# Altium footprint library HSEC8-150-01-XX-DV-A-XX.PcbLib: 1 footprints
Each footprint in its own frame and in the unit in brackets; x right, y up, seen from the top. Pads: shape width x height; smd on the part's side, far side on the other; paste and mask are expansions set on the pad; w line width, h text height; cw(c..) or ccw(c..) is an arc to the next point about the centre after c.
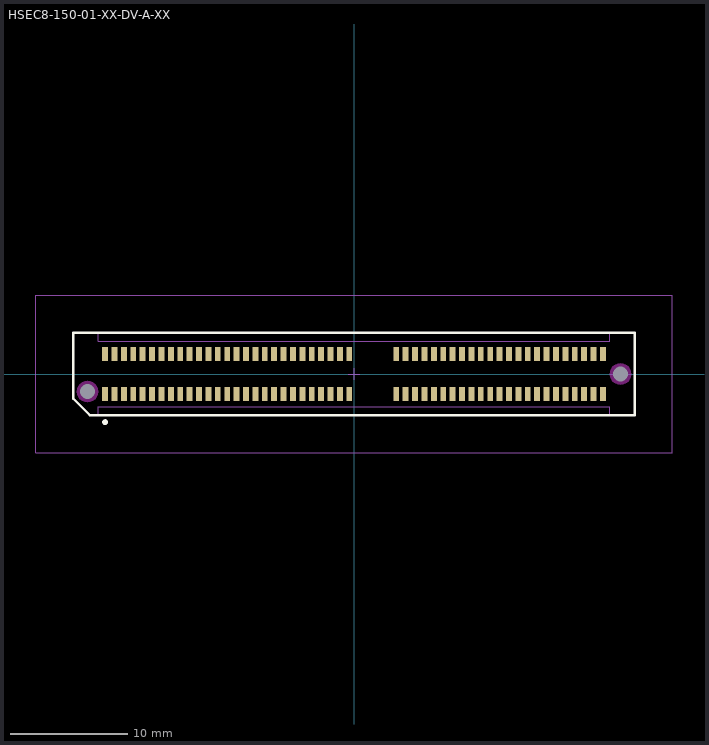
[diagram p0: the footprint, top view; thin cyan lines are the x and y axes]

## HSEC8-150-01-XX-DV-A-XX [mm] "0.80mm pitch, high-speed connector; socket (female), w/alignment pins, SMT"
height 7.98
pads (102):
  rect 0.5x1.2 smd mask+0: 1(-21.2,-1.7) 2(-21.2,1.7) 3(-20.4,-1.7) 4(-20.4,1.7) 5(-19.6,-1.7) 6(-19.6,1.7) 7(-18.8,-1.7) 8(-18.8,1.7) 9(-18,-1.7) 10(-18,1.7) 11(-17.2,-1.7) 12(-17.2,1.7) 13(-16.4,-1.7) 14(-16.4,1.7) 15(-15.6,-1.7) 16(-15.6,1.7) 17(-14.8,-1.7) 18(-14.8,1.7) 19(-14,-1.7) 20(-14,1.7) 21(-13.2,-1.7) 22(-13.2,1.7) 23(-12.4,-1.7) 24(-12.4,1.7) 25(-11.6,-1.7) 26(-11.6,1.7) 27(-10.8,-1.7) 28(-10.8,1.7) 29(-10,-1.7) 30(-10,1.7) 31(-9.2,-1.7) 32(-9.2,1.7) 33(-8.4,-1.7) 34(-8.4,1.7) 35(-7.6,-1.7) 36(-7.6,1.7) 37(-6.8,-1.7) 38(-6.8,1.7) 39(-6,-1.7) 40(-6,1.7) 41(-5.2,-1.7) 42(-5.2,1.7) 43(-4.4,-1.7) 44(-4.4,1.7) 45(-3.6,-1.7) 46(-3.6,1.7) 47(-2.8,-1.7) 48(-2.8,1.7) 49(-2,-1.7) 50(-2,1.7) 51(-1.2,-1.7) 52(-1.2,1.7) 53(-0.4,-1.7) 54(-0.4,1.7) 55(3.6,-1.7) 56(3.6,1.7) 57(4.4,-1.7) 58(4.4,1.7) 59(5.2,-1.7) 60(5.2,1.7) 61(6,-1.7) 62(6,1.7) 63(6.8,-1.7) 64(6.8,1.7) 65(7.6,-1.7) 66(7.6,1.7) 67(8.4,-1.7) 68(8.4,1.7) 69(9.2,-1.7) 70(9.2,1.7) 71(10,-1.7) 72(10,1.7) 73(10.8,-1.7) 74(10.8,1.7) 75(11.6,-1.7) 76(11.6,1.7) 77(12.4,-1.7) 78(12.4,1.7) 79(13.2,-1.7) 80(13.2,1.7) 81(14,-1.7) 82(14,1.7) 83(14.8,-1.7) 84(14.8,1.7) 85(15.6,-1.7) 86(15.6,1.7) 87(16.4,-1.7) 88(16.4,1.7) 89(17.2,-1.7) 90(17.2,1.7) 91(18,-1.7) 92(18,1.7) 93(18.8,-1.7) 94(18.8,1.7) 95(19.6,-1.7) 96(19.6,1.7) 97(20.4,-1.7) 98(20.4,1.7) 99(21.2,-1.7) 100(21.2,1.7)
  round 1 hole 1.3 unplated mask+0: 101(-22.7,-1.5) 102(22.7,0)
Top Overlay:
  circle w0.25: c-21.2,-4.1 r0.125
  lines w0.2: -23.9,-2.1 -23.9,3.5 23.9,3.5 23.9,-3.5 -22.5,-3.5 -23.9,-2.1
Keep-Out Layer:
  pour cut-out: 23.608,0 23.577,0.235 23.486,0.454 23.342,0.642 23.154,0.786 22.935,0.877 22.7,0.908 22.465,0.877 22.246,0.786 22.058,0.642 21.914,0.454 21.823,0.235 21.792,0 21.823,-0.235 21.914,-0.454 22.058,-0.642 22.246,-0.786 22.465,-0.877 22.7,-0.908 22.935,-0.877 23.154,-0.786 23.342,-0.642 23.486,-0.454 23.577,-0.235
  pour cut-out: -21.792,-1.5 -21.823,-1.265 -21.914,-1.046 -22.058,-0.858 -22.246,-0.714 -22.465,-0.623 -22.7,-0.592 -22.935,-0.623 -23.154,-0.714 -23.342,-0.858 -23.486,-1.046 -23.577,-1.265 -23.608,-1.5 -23.577,-1.735 -23.486,-1.954 -23.342,-2.142 -23.154,-2.286 -22.935,-2.377 -22.7,-2.408 -22.465,-2.377 -22.246,-2.286 -22.058,-2.142 -21.914,-1.954 -21.823,-1.735
Mechanical 12:
  lines w0.001: -23.9,-2.1 -23.9,3.5 23.9,3.5 23.9,-3.5 -22.5,-3.5 -23.9,-2.1
Mechanical 13:
  lines w0.1: -23.9,-2.1 -23.9,3.5 -21.8,3.5 -21.8,2.8 21.8,2.8 21.8,3.5 23.9,3.5 23.9,-3.5 21.8,-3.5 21.8,-2.8 -21.8,-2.8 -21.8,-3.5 -22.5,-3.5 -23.9,-2.1
  text ".Designator" at 0.127,0.254 h1.52
Mechanical 15:
  lines w0.05: -0.5,0 0.5,0 ; 0,-0.5 0,0.5 ; -27.1,-6.7 -27.1,6.7 27.1,6.7 27.1,-6.7 -27.1,-6.7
